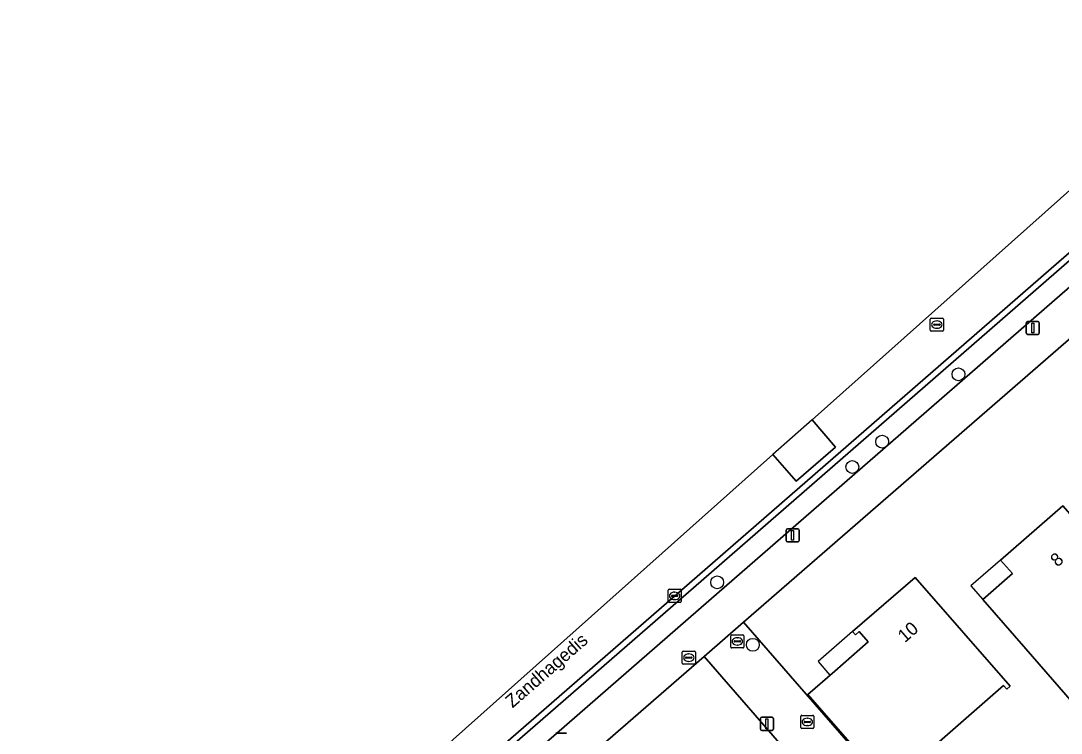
# Model space of a CAD drawing. Extents: x 155887 to 156869, y 383880 to 384678.
# Drawn here: x 156144.8 to 156224, y 384286.5 to 384340.8 of the extents above; entities that cross this region are included whole.
import ezdxf

# ---------------------------------------------------------------- set-up
doc = ezdxf.new("R2010")
doc.units = 0
for name, color, linetype in [('IMGEO_Boom', 7, 'Continuous'), ('IMGEO_Brandkraan', 7, 'Continuous'), ('IMGEO_Erf', 7, 'Continuous'), ('IMGEO_Kolk', 7, 'Continuous'), ('IMGEO_Lichtmast', 7, 'Continuous'), ('IMGEO_Openbare_ruimte_label', 7, 'Continuous'), ('IMGEO_Pand', 7, 'Continuous'), ('IMGEO_Pand_nummerreeks', 7, 'Continuous'), ('IMGEO_Pand_overbouw', 7, 'Continuous'), ('IMGEO_Parkeervlak_open', 7, 'Continuous'), ('IMGEO_Rijbaan_lokaal_gesloten', 7, 'Continuous'), ('IMGEO_Rijbaan_lokaal_open', 7, 'Continuous'), ('IMGEO_Rioolput', 7, 'Continuous'), ('IMGEO_Voetpad_open', 7, 'Continuous')]:
    doc.layers.add(name, color=color, linetype=linetype)

msp = doc.modelspace()

# ---------------------------------------------------------------- linework, layer by layer
at = {"layer": 'IMGEO_Boom'}
for centre in [(156216.193, 384313.836), (156210.379, 384308.709), (156208.107, 384306.778), (156197.811, 384297.985), (156200.524, 384293.227)]:
    msp.add_circle(centre, 0.489, dxfattribs=at)
at = {"layer": 'IMGEO_Brandkraan'}
for p, q in [((156195.146, 384291.822), (156195.146, 384292.674)), ((156195.221, 384292.748), (156196.073, 384292.748)), ((156195.634, 384292.528), (156195.659, 384292.528)), ((156196.147, 384292.674), (156196.147, 384291.822)), ((156196.073, 384291.748), (156195.221, 384291.748)), ((156195.405, 384292.242), (156195.405, 384292.254)), ((156195.843, 384292.205), (156195.445, 384292.205)), ((156195.448, 384292.291), (156195.846, 384292.291)), ((156195.657, 384291.968), (156195.632, 384291.968)), ((156195.889, 384292.254), (156195.889, 384292.242))]:
    msp.add_line(p, q, dxfattribs=at)
for points in [[(156195.146, 384291.822), (156195.146, 384292.674)], [(156195.221, 384292.748), (156196.073, 384292.748)], [(156196.147, 384292.674), (156196.147, 384291.822)], [(156196.073, 384291.748), (156195.221, 384291.748)]]:
    msp.add_lwpolyline(points, dxfattribs=at)
for centre, radius, start, end in [((156195.223, 384292.672), 0.0765, 91.55205, 178.44795), ((156195.223, 384292.672), 0.0765, 91.55205, 178.44795), ((156196.071, 384292.672), 0.0765, 1.55205, 88.44795), ((156196.071, 384292.672), 0.0765, 1.55205, 88.44795), ((156195.223, 384291.824), 0.0765, 181.55205, 268.44795), ((156195.223, 384291.824), 0.0765, 181.55205, 268.44795), ((156195.445, 384292.251), 0.0403, 85.87752, 175.75265), ((156195.442, 384292.241), 0.0366, 178.93798, 274.71019), ((156195.846, 384292.248), 0.043, 264.86636, 352.45326), ((156195.85, 384292.253), 0.0386, 1.73085, 96.63898), ((156196.071, 384291.824), 0.0765, 271.55205, 358.44795), ((156196.071, 384291.824), 0.0765, 271.55205, 358.44795)]:
    msp.add_arc(centre, radius, start, end, dxfattribs=at)
for centre, major_axis, ratio, start_param, end_param in [((156195.633, 384292.248), (-0.387, 0.002), 0.722429, 4.712389, 7.853982), ((156195.658, 384292.248), (-0.39, 0.002), 0.717154, 1.570796, 4.712389)]:
    msp.add_ellipse(centre, major_axis=major_axis, ratio=ratio, start_param=start_param, end_param=end_param, dxfattribs=at)
at = {"layer": 'IMGEO_Erf'}
for points in [[(156245.448, 384334.593), (156199.823, 384294.964), (156222.851, 384268.495), (156226.866, 384272.016)], [(156222.476, 384262.828), (156196.813, 384292.349), (156151.225, 384252.74)]]:
    msp.add_lwpolyline(points, dxfattribs=at)
for points in [[(156227.439, 384300.06), (156231.385, 384295.533), (156233.681, 384292.899), (156226.657, 384286.791), (156224.372, 384289.418), (156221.327, 384292.919), (156218.044, 384296.69), (156220.307, 384298.648), (156219.407, 384299.689), (156224.153, 384303.828)], [(156220.122, 384290.065), (156219.873, 384289.847), (156219.623, 384290.133), (156213.113, 384284.448), (156214.481, 384282.881), (156212.431, 384281.091), (156212.772, 384280.699), (156212.538, 384280.495), (156204.722, 384289.444), (156206.77, 384291.232), (156209.31, 384293.45), (156208.625, 384294.233), (156208.346, 384293.989), (156208.128, 384294.237), (156212.892, 384298.368)]]:
    msp.add_lwpolyline(points, close=True, dxfattribs=at)
at = {"layer": 'IMGEO_Kolk'}
for p, q in [((156194.07, 384296.53), (156194.07, 384297.382)), ((156194.145, 384297.456), (156194.997, 384297.456)), ((156194.558, 384297.236), (156194.583, 384297.236)), ((156195.071, 384297.382), (156195.071, 384296.53)), ((156194.997, 384296.456), (156194.145, 384296.456)), ((156194.329, 384296.95), (156194.329, 384296.962)), ((156194.767, 384296.913), (156194.369, 384296.913)), ((156194.372, 384296.999), (156194.77, 384296.999)), ((156194.581, 384296.676), (156194.556, 384296.676)), ((156194.813, 384296.962), (156194.813, 384296.95)), ((156198.924, 384293.985), (156199.776, 384293.985)), ((156198.849, 384293.059), (156198.849, 384293.911)), ((156199.108, 384293.479), (156199.108, 384293.491)), ((156199.546, 384293.442), (156199.148, 384293.442)), ((156199.151, 384293.528), (156199.549, 384293.528)), ((156199.36, 384293.205), (156199.335, 384293.205)), ((156199.337, 384293.765), (156199.362, 384293.765)), ((156199.592, 384293.491), (156199.592, 384293.479)), ((156199.85, 384293.911), (156199.85, 384293.059)), ((156199.776, 384292.985), (156198.924, 384292.985)), ((156204.177, 384286.928), (156204.177, 384287.78)), ((156204.252, 384287.854), (156205.104, 384287.854)), ((156205.178, 384287.78), (156205.178, 384286.928)), ((156205.104, 384286.854), (156204.252, 384286.854)), ((156204.436, 384287.348), (156204.436, 384287.36)), ((156204.874, 384287.311), (156204.476, 384287.311)), ((156204.479, 384287.397), (156204.877, 384287.397)), ((156204.688, 384287.074), (156204.663, 384287.074)), ((156204.665, 384287.634), (156204.69, 384287.634)), ((156204.92, 384287.36), (156204.92, 384287.348))]:
    msp.add_line(p, q, dxfattribs=at)
for points in [[(156194.07, 384296.53), (156194.07, 384297.382)], [(156194.145, 384297.456), (156194.997, 384297.456)], [(156195.071, 384297.382), (156195.071, 384296.53)], [(156194.997, 384296.456), (156194.145, 384296.456)], [(156198.924, 384293.985), (156199.776, 384293.985)], [(156198.849, 384293.059), (156198.849, 384293.911)], [(156199.85, 384293.911), (156199.85, 384293.059)], [(156199.776, 384292.985), (156198.924, 384292.985)], [(156204.177, 384286.928), (156204.177, 384287.78)], [(156204.252, 384287.854), (156205.104, 384287.854)], [(156205.178, 384287.78), (156205.178, 384286.928)], [(156205.104, 384286.854), (156204.252, 384286.854)]]:
    msp.add_lwpolyline(points, dxfattribs=at)
for centre, radius, start, end in [((156194.147, 384297.38), 0.0765, 91.55205, 178.44795), ((156194.147, 384297.38), 0.0765, 91.55205, 178.44795), ((156194.995, 384297.38), 0.0765, 1.55205, 88.44795), ((156194.995, 384297.38), 0.0765, 1.55205, 88.44795), ((156194.147, 384296.532), 0.0765, 181.55205, 268.44795), ((156194.147, 384296.532), 0.0765, 181.55205, 268.44795), ((156194.369, 384296.959), 0.0403, 85.87752, 175.75265), ((156194.366, 384296.949), 0.0366, 178.93798, 274.71019), ((156194.77, 384296.956), 0.043, 264.86636, 352.45326), ((156194.774, 384296.961), 0.0386, 1.73085, 96.63898), ((156194.995, 384296.532), 0.0765, 271.55205, 358.44795), ((156194.995, 384296.532), 0.0765, 271.55205, 358.44795), ((156198.926, 384293.909), 0.0765, 91.55205, 178.44795), ((156198.926, 384293.909), 0.0765, 91.55205, 178.44795), ((156199.774, 384293.909), 0.0765, 1.55205, 88.44795), ((156199.774, 384293.909), 0.0765, 1.55205, 88.44795), ((156199.148, 384293.488), 0.0403, 85.87752, 175.75265), ((156199.145, 384293.478), 0.0366, 178.93798, 274.71019), ((156199.549, 384293.485), 0.043, 264.86636, 352.45326), ((156199.553, 384293.49), 0.0386, 1.73085, 96.63898), ((156198.926, 384293.061), 0.0765, 181.55205, 268.44795), ((156198.926, 384293.061), 0.0765, 181.55205, 268.44795), ((156199.774, 384293.061), 0.0765, 271.55205, 358.44795), ((156199.774, 384293.061), 0.0765, 271.55205, 358.44795), ((156204.254, 384287.778), 0.0765, 91.55205, 178.44795), ((156204.254, 384287.778), 0.0765, 91.55205, 178.44795), ((156205.102, 384287.778), 0.0765, 1.55205, 88.44795), ((156205.102, 384287.778), 0.0765, 1.55205, 88.44795), ((156204.254, 384286.93), 0.0765, 181.55205, 268.44795), ((156204.254, 384286.93), 0.0765, 181.55205, 268.44795), ((156204.476, 384287.357), 0.0403, 85.87752, 175.75265), ((156204.473, 384287.347), 0.0366, 178.93798, 274.71019), ((156204.877, 384287.354), 0.043, 264.86636, 352.45326), ((156204.881, 384287.359), 0.0386, 1.73085, 96.63898), ((156205.102, 384286.93), 0.0765, 271.55205, 358.44795), ((156205.102, 384286.93), 0.0765, 271.55205, 358.44795)]:
    msp.add_arc(centre, radius, start, end, dxfattribs=at)
for centre, major_axis, ratio, start_param, end_param in [((156194.557, 384296.956), (-0.387, 0.002), 0.722429, 4.712389, 7.853982), ((156194.582, 384296.956), (-0.39, 0.002), 0.717154, 1.570796, 4.712389), ((156199.336, 384293.485), (-0.387, 0.002), 0.722429, 4.712389, 7.853982), ((156199.361, 384293.485), (-0.39, 0.002), 0.717154, 1.570796, 4.712389), ((156204.664, 384287.354), (-0.387, 0.002), 0.722429, 4.712389, 7.853982), ((156204.689, 384287.354), (-0.39, 0.002), 0.717154, 1.570796, 4.712389)]:
    msp.add_ellipse(centre, major_axis=major_axis, ratio=ratio, start_param=start_param, end_param=end_param, dxfattribs=at)
at = {"layer": 'IMGEO_Lichtmast'}
for p, q in [((156221.364, 384316.965), (156221.364, 384317.765)), ((156221.364, 384317.765), (156221.364, 384316.965)), ((156221.464, 384317.865), (156222.254, 384317.865)), ((156222.254, 384317.865), (156221.464, 384317.865)), ((156222.354, 384317.765), (156222.354, 384316.965)), ((156222.354, 384316.965), (156222.354, 384317.765)), ((156222.254, 384316.865), (156221.464, 384316.865)), ((156221.464, 384316.865), (156222.254, 384316.865)), ((156203.064, 384301.165), (156203.064, 384301.965)), ((156203.064, 384301.965), (156203.064, 384301.165)), ((156203.164, 384302.065), (156203.954, 384302.065)), ((156203.954, 384302.065), (156203.164, 384302.065)), ((156204.054, 384301.965), (156204.054, 384301.165)), ((156204.054, 384301.165), (156204.054, 384301.965)), ((156203.954, 384301.065), (156203.164, 384301.065)), ((156203.164, 384301.065), (156203.954, 384301.065)), ((156201.201, 384287.707), (156201.991, 384287.707)), ((156201.991, 384287.707), (156201.201, 384287.707)), ((156201.101, 384286.807), (156201.101, 384287.607)), ((156201.101, 384287.607), (156201.101, 384286.807)), ((156202.091, 384287.607), (156202.091, 384286.807)), ((156202.091, 384286.807), (156202.091, 384287.607)), ((156185.529, 384286.494), (156186.319, 384286.494)), ((156186.319, 384286.494), (156185.529, 384286.494)), ((156201.991, 384286.707), (156201.201, 384286.707)), ((156201.201, 384286.707), (156201.991, 384286.707))]:
    msp.add_line(p, q, dxfattribs=at)
for points in [[(156221.784, 384317.74), (156221.934, 384317.74), (156221.934, 384316.99), (156221.784, 384316.99), (156221.784, 384317.74)], [(156203.484, 384301.94), (156203.634, 384301.94), (156203.634, 384301.19), (156203.484, 384301.19), (156203.484, 384301.94)], [(156201.521, 384287.582), (156201.671, 384287.582), (156201.671, 384286.832), (156201.521, 384286.832), (156201.521, 384287.582)]]:
    msp.add_lwpolyline(points, dxfattribs=at)
for centre, start, end in [((156221.464, 384317.765), 90, 180), ((156221.464, 384317.765), 90, 180), ((156222.254, 384317.765), 0, 90), ((156222.254, 384317.765), 360, 90), ((156221.464, 384316.965), 180, 270), ((156221.464, 384316.965), 180, 270), ((156222.254, 384316.965), 270, 0), ((156222.254, 384316.965), 270, 0), ((156203.164, 384301.965), 90, 180), ((156203.164, 384301.965), 90, 180), ((156203.954, 384301.965), 0, 90), ((156203.954, 384301.965), 360, 90), ((156203.164, 384301.165), 180, 270), ((156203.164, 384301.165), 180, 270), ((156203.954, 384301.165), 270, 0), ((156203.954, 384301.165), 270, 0), ((156201.201, 384287.607), 90, 180), ((156201.201, 384287.607), 90, 180), ((156201.991, 384287.607), 0, 90), ((156201.991, 384287.607), 360, 90), ((156201.201, 384286.807), 180, 270), ((156201.201, 384286.807), 180, 270), ((156201.991, 384286.807), 270, 0), ((156201.991, 384286.807), 270, 0)]:
    msp.add_arc(centre, 0.1, start, end, dxfattribs=at)
at = {"layer": 'IMGEO_Pand'}
for points in [[(156227.439, 384300.06), (156224.153, 384303.828), (156219.407, 384299.689), (156220.307, 384298.648), (156218.044, 384296.69), (156221.327, 384292.919), (156224.372, 384289.418), (156226.657, 384286.791), (156233.681, 384292.899), (156231.385, 384295.533)], [(156206.77, 384291.232), (156204.722, 384289.444), (156212.538, 384280.495), (156212.772, 384280.699), (156212.431, 384281.091), (156214.481, 384282.881), (156213.113, 384284.448), (156219.623, 384290.133), (156219.873, 384289.847), (156220.122, 384290.065), (156212.892, 384298.368), (156208.128, 384294.237), (156208.346, 384293.989), (156208.625, 384294.233), (156209.31, 384293.45)]]:
    msp.add_lwpolyline(points, close=True, dxfattribs=at)
at = {"layer": 'IMGEO_Pand_overbouw'}
for points in [[(156218.044, 384296.69), (156220.307, 384298.648), (156219.407, 384299.689), (156217.148, 384297.719)], [(156205.492, 384291.951), (156206.401, 384290.91), (156206.77, 384291.232), (156209.31, 384293.45), (156208.625, 384294.233), (156208.346, 384293.989), (156208.128, 384294.237)]]:
    msp.add_lwpolyline(points, close=True, dxfattribs=at)
at = {"layer": 'IMGEO_Parkeervlak_open'}
msp.add_lwpolyline([(156243.423, 384336.821), (156242.433, 384337.97), (156241.908, 384337.514), (156196.003, 384297.575), (156148.331, 384256.132), (156149.366, 384254.957), (156197.186, 384296.583), (156243.39, 384336.792)], close=True, dxfattribs=at)
at = {"layer": 'IMGEO_Rijbaan_lokaal_gesloten'}
msp.add_lwpolyline([(156145.084, 384256.945), (156146.522, 384255.236), (156148.027, 384256.477), (156195.701, 384297.922), (156241.611, 384337.864), (156239.143, 384340.771), (156205.037, 384310.375), (156205.037, 384310.375), (156206.836, 384308.286), (156203.826, 384305.7), (156202.059, 384307.721), (156202.059, 384307.721), (156165.99, 384275.576), (156165.99, 384275.576), (156167.39, 384273.979), (156164.424, 384271.419), (156163.064, 384272.968), (156163.064, 384272.968)], close=True, dxfattribs=at)
at = {"layer": 'IMGEO_Rijbaan_lokaal_open'}
for points in [[(156196.003, 384297.575), (156241.908, 384337.514), (156242.433, 384337.97), (156242.133, 384338.318), (156241.611, 384337.864), (156195.701, 384297.922), (156148.027, 384256.477), (156146.522, 384255.236), (156146.818, 384254.885), (156147.461, 384255.402), (156148.331, 384256.132)], [(156202.059, 384307.721), (156202.059, 384307.721), (156203.826, 384305.7), (156206.836, 384308.286), (156205.037, 384310.375), (156205.037, 384310.375)], [(156238.931, 384250), (156225.482, 384265.463), (156222.851, 384268.495), (156199.823, 384294.964), (156196.813, 384292.349), (156222.476, 384262.828), (156233.627, 384250), (156238.811, 384244.035), (156239.812, 384242.902), (156242.8, 384239.463), (156245.758, 384242.109), (156242.787, 384245.529), (156241.836, 384246.66)]]:
    msp.add_lwpolyline(points, close=True, dxfattribs=at)
at = {"layer": 'IMGEO_Rioolput'}
for p, q in [((156214.048, 384317.198), (156214.048, 384318.05)), ((156214.123, 384318.124), (156214.975, 384318.124)), ((156214.536, 384317.904), (156214.561, 384317.904)), ((156215.049, 384318.05), (156215.049, 384317.198)), ((156214.975, 384317.124), (156214.123, 384317.124)), ((156214.307, 384317.618), (156214.307, 384317.63)), ((156214.745, 384317.581), (156214.347, 384317.581)), ((156214.35, 384317.667), (156214.748, 384317.667)), ((156214.559, 384317.344), (156214.534, 384317.344)), ((156214.791, 384317.63), (156214.791, 384317.618))]:
    msp.add_line(p, q, dxfattribs=at)
for points in [[(156214.048, 384317.198), (156214.048, 384318.05)], [(156214.123, 384318.124), (156214.975, 384318.124)], [(156215.049, 384318.05), (156215.049, 384317.198)], [(156214.975, 384317.124), (156214.123, 384317.124)]]:
    msp.add_lwpolyline(points, dxfattribs=at)
for centre, radius, start, end in [((156214.125, 384318.048), 0.0765, 91.55205, 178.44795), ((156214.125, 384318.048), 0.0765, 91.55205, 178.44795), ((156214.973, 384318.048), 0.0765, 1.55205, 88.44795), ((156214.973, 384318.048), 0.0765, 1.55205, 88.44795), ((156214.125, 384317.2), 0.0765, 181.55205, 268.44795), ((156214.125, 384317.2), 0.0765, 181.55205, 268.44795), ((156214.347, 384317.627), 0.0403, 85.87752, 175.75265), ((156214.344, 384317.617), 0.0366, 178.93798, 274.71019), ((156214.748, 384317.624), 0.043, 264.86636, 352.45326), ((156214.752, 384317.629), 0.0386, 1.73085, 96.63898), ((156214.973, 384317.2), 0.0765, 271.55205, 358.44795), ((156214.973, 384317.2), 0.0765, 271.55205, 358.44795)]:
    msp.add_arc(centre, radius, start, end, dxfattribs=at)
for centre, major_axis, ratio, start_param, end_param in [((156214.535, 384317.624), (-0.387, 0.002), 0.722429, 4.712389, 7.853982), ((156214.56, 384317.624), (-0.39, 0.002), 0.717154, 1.570796, 4.712389)]:
    msp.add_ellipse(centre, major_axis=major_axis, ratio=ratio, start_param=start_param, end_param=end_param, dxfattribs=at)
at = {"layer": 'IMGEO_Voetpad_open'}
for points in [[(156196.813, 384292.349), (156199.823, 384294.964), (156245.448, 384334.593), (156247.015, 384335.884), (156248.065, 384336.788), (156246.616, 384338.427), (156245.586, 384337.534), (156245.01, 384338.202), (156243.423, 384336.821), (156243.39, 384336.792), (156197.186, 384296.583), (156149.366, 384254.957), (156148.331, 384256.132), (156147.461, 384255.402), (156146.818, 384254.885), (156148.442, 384252.972), (156145.06, 384250), (156144.753, 384249.73)], [(156145.532, 384247.791), (156148.072, 384250), (156149.771, 384251.478), (156151.225, 384252.74), (156196.813, 384292.349)]]:
    msp.add_lwpolyline(points, dxfattribs=at)

# ---------------------------------------------------------------- texts
at = {"layer": 'IMGEO_Openbare_ruimte_label'}
msp.add_text('Zandhagedis', height=1, rotation=40.98653, dxfattribs=at).set_placement((156182.213, 384288.372))
at = {"layer": 'IMGEO_Pand_nummerreeks'}
for s, rotation, p in [('8', 41.09253, (156223.731, 384299.108)), ('10', 40.92949, (156212.105, 384293.345))]:
    msp.add_text(s, height=1, rotation=rotation, dxfattribs=at).set_placement(p)

doc.saveas('drawing.dxf')
